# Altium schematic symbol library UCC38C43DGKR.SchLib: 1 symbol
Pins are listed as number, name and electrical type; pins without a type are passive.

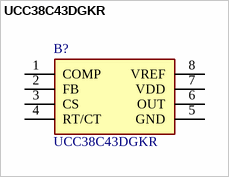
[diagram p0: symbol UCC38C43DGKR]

## UCC38C43DGKR
designator B?
BiCMOS Low-Power Current Mode PWM Controller; Manufacturer_Name: Texas Instruments; Geometry.Height: 1.1mm
footprint SOP65P490X110-8N
pins: 1 COMP, 2 FB, 3 CS, 4 RT/CT, 5 GND, 6 OUT, 7 VDD, 8 VREF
